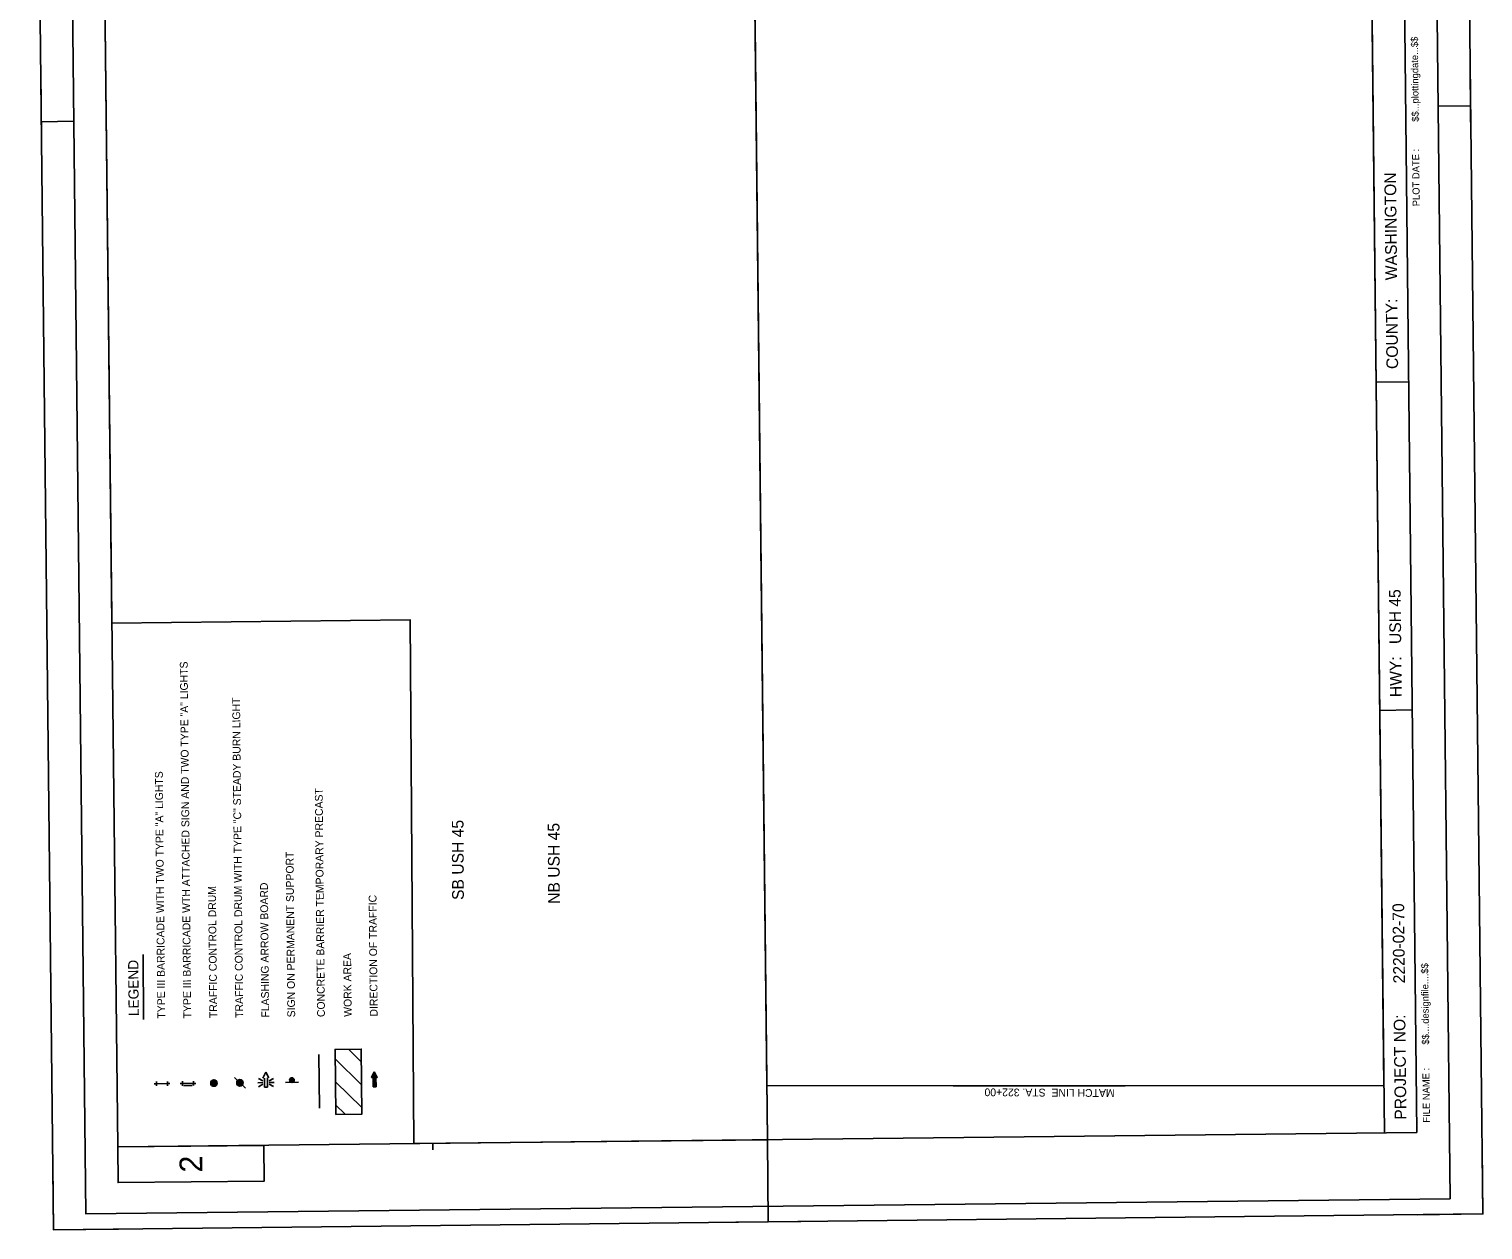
# Model space of a CAD drawing. Extents: x 359851 to 360969, y 155041 to 156753.
# Drawn here: x 359851 to 360969, y 155041 to 155965 of the extents above; entities that cross this region are included whole.
import ezdxf

# ---------------------------------------------------------------- set-up
doc = ezdxf.new("R2010")
doc.units = 0
for name, color, linetype in [('Default', 7, 'Continuous'), ('P_ALI_100_Equation', 7, 'Continuous'), ('P_ALI_100_PIData', 7, 'Continuous'), ('P_ALI_100_Tic', 7, 'Continuous'), ('P_ALI_20', 7, 'Continuous'), ('P_ALI_200_Sta', 7, 'Continuous'), ('P_ALI_20_Equation', 7, 'Continuous'), ('P_ALI_20_Tic', 7, 'Continuous'), ('P_ALI_50_Equation', 7, 'Continuous'), ('P_ALI_50_PIData', 7, 'Continuous'), ('P_ALI_50_Tic', 7, 'Continuous')]:
    doc.layers.add(name, color=color, linetype=linetype)

msp = doc.modelspace()

# ---------------------------------------------------------------- linework, layer by layer
msp.add_lwpolyline([(359869.4, 155041.2), (359850.5, 156741), (360950.5, 156753.3), (360969.3, 155053.4), (359869.4, 155041.2)])
at = {"layer": 'Default'}
for points in [[(360418.2, 155151.9), (360893.2, 155152.2), (360876.6, 156652.1), (360401.5, 156651.8)], [(360418.2, 155151.9), (360893.2, 155152.2), (360876.6, 156652.1), (360401.5, 156651.8)], [(360418.2, 155151.9), (360893.2, 155152.2), (360876.6, 156652.1), (360401.5, 156651.8)], [(359914.2, 155507.8), (360143.8, 155510.4), (360146.5, 155107.5), (360418.7, 155110.5), (360401.8, 156632.5), (359901.7, 156632.1)], [(359914.2, 155507.8), (360143.8, 155510.4), (360146.5, 155107.5), (360418.7, 155110.5), (360401.8, 156632.5), (359901.7, 156632.1)], [(359914.2, 155507.8), (360143.8, 155510.4), (360146.5, 155107.5), (360418.7, 155110.5), (360401.8, 156632.5), (359901.7, 156632.1)]]:
    msp.add_lwpolyline(points, close=True, dxfattribs=at)
at = {"layer": 'P_ALI_100_Equation'}
for p, q in [((360106.3, 155152.8), (360086.1, 155172.7)), ((360106.2, 155170.5), (360096.4, 155180.1)), ((360030.5, 155158), (360032.7, 155162.4)), ((360032.7, 155162.4), (360035, 155158.1)), ((359948.6, 155153.6), (359946.9, 155153.6)), ((359946.9, 155153.6), (359948.6, 155153.6)), ((359948.6, 155153.6), (359948.6, 155155.3)), ((359948.6, 155155.3), (359948.6, 155153.6)), ((359957.1, 155153.7), (359948.6, 155153.6)), ((359948.6, 155153.6), (359948.6, 155151.9)), ((359948.6, 155151.9), (359948.6, 155153.6)), ((359957.1, 155155.4), (359957.1, 155153.7)), ((359957.1, 155153.7), (359957.1, 155155.4)), ((359957.1, 155153.7), (359958.8, 155153.7)), ((359958.8, 155153.7), (359957.1, 155153.7)), ((359957.1, 155153.7), (359957.1, 155152)), ((359957.1, 155152), (359957.1, 155153.7)), ((359968.6, 155153.8), (359966.9, 155153.8)), ((359966.9, 155153.8), (359968.6, 155153.8)), ((359968.6, 155153.8), (359968.6, 155155.5)), ((359968.6, 155155.5), (359968.6, 155153.8)), ((359977.1, 155153.9), (359968.6, 155153.8)), ((359968.6, 155153.8), (359968.6, 155152.1)), ((359968.6, 155152.1), (359968.6, 155153.8)), ((359976.1, 155152.2), (359969.6, 155152.1)), ((359977.1, 155155.6), (359977.1, 155153.9)), ((359977.1, 155153.9), (359977.1, 155155.6)), ((359977.1, 155153.9), (359978.8, 155153.9)), ((359978.8, 155153.9), (359977.1, 155153.9)), ((359977.1, 155153.9), (359977.1, 155152.2)), ((359977.1, 155152.2), (359977.1, 155153.9)), ((360017.1, 155150.1), (360008.5, 155158.5)), ((360030.3, 155154.5), (360026.6, 155154.4)), ((360030.3, 155155.7), (360027, 155157.6)), ((360030.3, 155153.2), (360027.1, 155151.3)), ((360031.7, 155150.9), (360031.7, 155158)), ((360034, 155150.9), (360031.7, 155150.9)), ((360033.9, 155158.1), (360034, 155150.9)), ((360035.3, 155155.8), (360038.6, 155157.7)), ((360035.3, 155154.5), (360039.1, 155154.5)), ((360035.4, 155153.3), (360038.6, 155151.4)), ((360057.8, 155154.7), (360047.8, 155154.6)), ((360106.5, 155135.2), (360086.3, 155155)), ((360093.8, 155130.1), (360086.4, 155137.3))]:
    msp.add_line(p, q, dxfattribs=at)
msp.add_lwpolyline([(360086.5, 155130), (360086, 155180), (360106.1, 155180.2), (360106.6, 155130.2)], close=True, dxfattribs=at)
for centre, radius in [((359992.8, 155154.1), 2.5), ((359992.8, 155154.1), 2), ((359992.8, 155154.1), 1.5), ((359992.8, 155154.1), 1), ((359992.8, 155154.1), 0.5), ((359992.8, 155154.1), 0.25), ((360012.8, 155154.3), 2.5), ((360012.8, 155154.3), 2), ((360012.8, 155154.3), 1.5), ((360012.8, 155154.3), 1), ((360012.8, 155154.3), 0.5), ((360012.8, 155154.3), 0.25), ((360052.8, 155156.4), 1.75), ((360052.8, 155156.4), 1), ((360052.8, 155156.4), 0.25)]:
    msp.add_circle(centre, radius, dxfattribs=at)
at = {"layer": 'P_ALI_100_PIData'}
msp.add_line((359938.7, 155203), (359938.2, 155252.9), dxfattribs=at)
at = {"layer": 'P_ALI_100_Tic'}
msp.add_line((360074, 155134.7), (360073.5, 155176.1), dxfattribs=at)
at = {"layer": 'P_ALI_20'}
for p, q in [((360418.7, 155110.5), (360401.2, 156685.4)), ((360893.6, 155115.8), (360876.1, 156690.7)), ((360918.6, 155116.1), (360901.1, 156691)), ((359918.7, 155105), (359901.2, 156679.9)), ((360960.1, 155880.8), (360959.6, 155930.8)), ((359860.2, 155868.6), (359859.7, 155918.6)), ((360959.9, 155905.8), (360934.9, 155905.5)), ((359859.9, 155893.6), (359884.9, 155893.9)), ((360912.2, 155693.5), (360887.2, 155693.3)), ((360915, 155441.1), (360890, 155440.8)), ((360418.3, 155148), (360418.3, 155148)), ((360918.6, 155116.1), (359918.7, 155105)), ((360161.2, 155107.7), (360161.2, 155102.7)), ((360419.4, 155047.3), (360418.7, 155110.5)), ((360969.3, 155053.4), (360968.8, 155103.4)), ((359869.4, 155041.2), (359868.9, 155091.2)), ((360444.4, 155047.5), (360394.4, 155047)), ((360969.3, 155053.4), (360919.3, 155052.8)), ((359919.4, 155041.7), (359869.4, 155041.2))]:
    msp.add_line(p, q, dxfattribs=at)
msp.add_lwpolyline([(359918.7, 155105), (359919, 155077.5), (360031.5, 155078.7), (360031.2, 155106.2)], close=True, dxfattribs=at)
at = {"layer": 'P_ALI_200_Sta'}
msp.add_line((360418.7, 155110.5), (360401.2, 156685.4), dxfattribs=at)
at = {"layer": 'P_ALI_20_Equation'}
for p, q in [((360116.2, 155162.8), (360114, 155158.4)), ((360114.7, 155158.4), (360114.7, 155159.7)), ((360115.2, 155158.4), (360115.1, 155160.6)), ((360115.7, 155151.3), (360115.6, 155161.5)), ((360116.1, 155151.3), (360116, 155162.4)), ((360116.2, 155162.8), (360118.5, 155158.4)), ((360116.6, 155151.3), (360116.5, 155162.3)), ((360117, 155151.3), (360116.9, 155161.5)), ((360117.4, 155158.5), (360117.4, 155160.6)), ((360117.9, 155158.5), (360117.9, 155159.7)), ((360114, 155158.4), (360118.5, 155158.4)), ((360114.3, 155158.4), (360114.3, 155158.8)), ((360115.2, 155151.3), (360115.2, 155158.4)), ((360115.2, 155151.3), (360117.5, 155151.3)), ((360116.4, 155151.3), (360116.4, 155151.3)), ((360117.5, 155151.3), (360117.4, 155158.4)), ((360118.3, 155158.5), (360118.3, 155158.9))]:
    msp.add_line(p, q, dxfattribs=at)
at = {"layer": 'P_ALI_20_Tic'}
msp.add_lwpolyline([(359869.4, 155041.2), (359850.5, 156741), (360950.5, 156753.3), (360969.3, 155053.4)], close=True, dxfattribs=at)
at = {"layer": 'P_ALI_50_Equation'}
msp.add_line((360561.7, 155152), (360694, 155152.1), dxfattribs=at)
at = {"layer": 'P_ALI_50_Tic'}
for points in [[(360969.3, 155053.4), (360950.5, 156753.3), (359850.5, 156741), (359869.4, 155041.2)], [(360944.2, 155065.1), (360925.8, 156720), (359875.9, 156708.3), (359894.3, 155053.4)]]:
    msp.add_lwpolyline(points, close=True, dxfattribs=at)

# ---------------------------------------------------------------- texts
at = {"layer": 'P_ALI_100_PIData'}
for s, height, p in [('TYPE III BARRICADE WTH ATTACHED SIGN AND TWO TYPE "A" LIGHTS', 6, (359975.3, 155203.9)), ('TRAFFIC CONTROL DRUM WITH TYPE "C" STEADY BURN LIGHT', 6, (360015.3, 155204.3)), ('TYPE III BARRICADE WITH TWO TYPE "A" LIGHTS', 6, (359955.3, 155203.7)), ('CONCRETE BARRIER TEMPORARY PRECAST', 6, (360078.2, 155204.9)), ('SIGN ON PERMANENT SUPPORT', 6, (360055.3, 155204.7)), ('TRAFFIC CONTROL DRUM', 6, (359995.3, 155204.1)), ('FLASHING ARROW BOARD', 6, (360035.3, 155204.5)), ('DIRECTION OF TRAFFIC', 6, (360118.8, 155205.3)), ('LEGEND', 7.88, (359935, 155205.6)), ('WORK AREA', 6, (360098.8, 155205.1))]:
    msp.add_text(s, height=height, rotation=90.5775, dxfattribs=at).set_placement(p)
at = {"layer": 'P_ALI_20'}
for s, height, p in [('$$...plottingdate...$$', 5.4, (360920, 155893.6)), ('PLOT DATE :', 5.4, (360920.7, 155828.6)), (' WASHINGTON', 9, (360903.4, 155768.4)), ('COUNTY:', 9, (360904.1, 155703.4)), (' USH 45', 9, (360906.5, 155488.5)), ('HWY:', 9, (360906.9, 155451)), (' 2220-02-70', 9, (360909.4, 155227.5)), ('$$....designfile....$$', 5.4, (360927.9, 155183.7)), ('PROJECT NO:', 9, (360910.5, 155126)), ('FILE NAME :', 5.4, (360928.6, 155123.7)), ('2', 17.5, (359983.9, 155085.4))]:
    msp.add_text(s, height=height, rotation=90.6368, dxfattribs=at).set_placement(p)
at = {"layer": 'P_ALI_50_PIData'}
for s, height, rotation, p in [('SB USH 45', 9, 90.2285, (360185.1, 155295)), ('NB USH 45', 9, 90.2702, (360259, 155292)), ('MATCH LINE  STA. 322+00', 6, 179.6332, (360685.9, 155149.4))]:
    msp.add_text(s, height=height, rotation=rotation, dxfattribs=at).set_placement(p)

doc.saveas('drawing.dxf')
